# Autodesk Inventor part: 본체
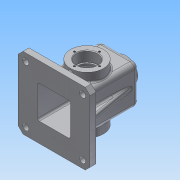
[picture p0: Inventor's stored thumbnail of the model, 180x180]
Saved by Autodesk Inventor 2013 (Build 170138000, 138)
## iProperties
Created: 2018-10
Part Number: 본체
Material: 알루미늄 6061
Document SubType Name: Modeling
Designer: Administrator
Density: 2.71 g/cm^3
Mass: 797.172 g
Surface Area: 899.5 cm^2
Volume: 294.16 cm^3
Author: Administrator
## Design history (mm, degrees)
sketch "스케치1"
  geometry: L1 (32.5, -32.5)-(-32.5, -32.5); L2 (-32.5, -32.5)-(-32.5, 32.5); L3 (-32.5, 32.5)-(32.5, 32.5); L4 (32.5, 32.5)-(32.5, -32.5); L5 (32.5, -32.5)-(-32.5, 32.5); L6 (-32.5, -32.5)-(32.5, 32.5); 1 further point
  constraints: 12 end point, 2 midpoint, 2 parallel, 1 horizontal, 1 perpendicular
  dimensions: "d0" = 65 distance of L2.end L3.end; "d1" = 65 distance of L1.end L2.end
extrude "돌출1" new body sketch "스케치1" stored distance "d2" = 110; taper "d3" = 0 deg
sketch "스케치2"
  geometry: L1 (-27.5, 27.5)-(27.5, 27.5); L2 (27.5, 27.5)-(27.5, -27.5); L3 (27.5, -27.5)-(-27.5, -27.5); L4 (-27.5, -27.5)-(-27.5, 27.5); L5 (-27.5, 27.5)-(27.5, -27.5); L6 (27.5, 27.5)-(-27.5, -27.5); 1 further point
  constraints: 12 end point, 2 midpoint, 2 parallel, 1 horizontal, 1 perpendicular
  dimensions: "d4" = 55 distance of L2.end L3.end; "d5" = 55 distance of L1.end L2.end
extrude "돌출2" cut sketch "스케치2" distance "d6" = 105; taper "d7" = 0 deg
fillet "모깎기1" dims "d8" = 8
sketch "스케치3"
  geometry: L1 (57, 0)-(49, 0) reference; C1 r 27.5 at (24.5, 55); 1 further point
  constraints: 1 centre point, 1 coincident
  dimensions: "d9" = 55 diameter of C1; "d10" = 55 distance from line of L1 C1.centre
extrude "돌출3" join sketch "스케치3" distance "d11" = 15; taper "d12" = 0 deg
sketch "스케치4"
  geometry: C1 r 27.5 at (0, 0) reference; 1 further point
  constraints: 1 coincident
hole "구멍1" sketch "스케치4" at (0, 0) diameter "d13" = 30; stored, may be unused: countersink angle "d17" = 90 deg, drill point angle "d19" = 0 deg; dims "d14" = 6, "d15" = 35, "d16" = 17, "d18" = 20
sketch "스케치5"
  geometry: C1 r 17.5 at (0, 0) reference; 1 further point
  constraints: 1 vertical alignment
  dimensions: "d20" = 21 distance of C1.centre point (0, 21)
hole "구멍2" sketch "스케치5" at (0, 21) diameter "d21" = 3.242; stored, may be unused: countersink angle "d25" = 90 deg, drill point angle "d27" = 118 deg; dims "d22" = 8, "d23" = 35, "d24" = 17, "d26" = 10
chamfer "모따기1" distance "d31" = 1; stored, may be unused: second distance "d32" = 2, angle "d33" = 45 deg
fillet "모깎기2" dims "d34" = 0.3
fillet "모깎기3" dims "d35" = 3
chamfer "모따기2" distance "d36" = 1; stored, may be unused: second distance "d37" = 2, angle "d38" = 45 deg
fillet "모깎기4" dims "d39" = 0.3
fillet "모깎기5" dims "d40" = 3
node "작업 평면1"
sketch "스케치6"
  geometry: C1 r 20 at (0, 0); 1 further point
  constraints: 1 centre point, 1 coincident
  dimensions: "d42" = 40 diameter of C1
extrude "돌출4" join sketch "스케치6" stored distance "d43" = 15; taper "d44" = 7 deg
sketch "스케치7"
  geometry: C1 r 20 at (0, 0) reference; 1 further point
  constraints: 1 coincident
hole "구멍3" sketch "스케치7" at (0, 0) diameter "d45" = 22.835; stored, may be unused: countersink angle "d49" = 90 deg, drill point angle "d51" = 118 deg; dims "d46" = 8, "d47" = 35, "d48" = 17, "d50" = 10
chamfer "모따기3" distance "d52" = 1; stored, may be unused: second distance "d53" = 2, angle "d54" = 45 deg
fillet "모깎기6" dims "d55" = 3
fillet "모깎기7" dims "d56" = 3
fillet "모깎기8" dims "d57" = 3
sketch "스케치8"
  geometry: L1 (-24.5, -32.5)-(24.5, -32.5) reference; L2 (32.5, -24.5)-(32.5, 24.5) reference; L3 (24.5, 32.5)-(-24.5, 32.5) reference; L4 (-32.5, 24.5)-(-32.5, -24.5) reference; L5 (60, 60)-(-60, 60); L6 (-60, 60)-(-60, -60); L7 (-60, -60)-(60, -60); L8 (60, -60)-(60, 60); L9 (60, 60)-(-60, -60); L10 (-60, 60)-(60, -60); A1 r 8 centre (24.5, -24.5) between (24.5, -32.5) and (32.5, -24.5) reference; A2 r 8 centre (24.5, 24.5) between (32.5, 24.5) and (24.5, 32.5) reference; A3 r 8 centre (-24.5, 24.5) between (-24.5, 32.5) and (-32.5, 24.5) reference; A4 r 8 centre (-24.5, -24.5) between (-32.5, -24.5) and (-24.5, -32.5) reference; 1 further point
  constraints: 12 end point, 2 midpoint, 2 parallel, 1 horizontal, 1 perpendicular
  dimensions: "d58" = 120 distance of L7.end L6.end; "d59" = 120 distance of L6.end L5.end
extrude "돌출5" join sketch "스케치8" distance "d60" = 10; taper "d61" = 0 deg
chamfer "모따기4" distance "d62" = 8; stored, may be unused: second distance "d63" = 2, angle "d64" = 45 deg
sketch "스케치9"
  geometry: L1 (-47.5, 47.5)-(47.5, 47.5); L2 (47.5, 47.5)-(47.5, -47.5); L3 (47.5, -47.5)-(-47.5, -47.5); L4 (-47.5, -47.5)-(-47.5, 47.5); L5 (-47.5, 47.5)-(47.5, -47.5); L6 (47.5, 47.5)-(-47.5, -47.5); 7 further points
  constraints: 12 end point, 5 coincident, 3 midpoint, 2 parallel, 1 horizontal, 1 perpendicular
  dimensions: "d65" = 95 distance of L2.end L3.end; "d66" = 95 distance of L1.end L2.end
hole "구멍4" sketch "스케치9" at (-47.5, 47.5), (47.5, 47.5), (-47.5, -47.5), (47.5, -47.5) diameter "d67" = 10; stored, may be unused: countersink angle "d71" = 90 deg, drill point angle "d73" = 118 deg; dims "d68" = 8, "d69" = 35, "d70" = 17, "d72" = 10
sketch "스케치10"
  geometry: L1 (-12.418, 65)-(-11.418, 64) reference; L2 (-11.418, 64)-(-11.418, 50) reference; L3 (-11.418, 50)-(-24.5, 50) reference; L4 (-27.5, 47)-(-27.5, -55) reference; L5 (-27.5, -55)-(-60, -55) reference; L6 (-60, -55)-(-60, -45) reference; L7 (-60, -45)-(-32.5, -45) reference; L8 (-32.5, -45)-(-32.5, 47) reference; L9 (-24.5, 55)-(-23.882, 55) reference; L10 (-20.904, 57.634)-(-20, 65) reference; L11 (-20, 65)-(-12.418, 65) reference; L12 (11.418, 64)-(12.418, 65) reference; L13 (12.418, 65)-(20, 65) reference; L14 (20, 65)-(20.904, 57.634) reference; L15 (23.882, 55)-(24.5, 55) reference; L16 (32.5, 47)-(32.5, -45) reference; L17 (32.5, -45)-(60, -45) reference; L18 (60, -45)-(60, -55) reference; L19 (60, -55)-(27.5, -55) reference; L20 (27.5, -55)-(27.5, 47) reference; L21 (24.5, 50)-(11.418, 50) reference; L22 (11.418, 50)-(11.418, 64) reference; L23 (-48, -45)-(-41.054, -5.608); L24 (-48, -45)-(-8, -45); A1 r 3 centre (-24.5, 47) between (-24.5, 50) and (-27.5, 47) reference; A2 r 8 centre (-24.5, 47) between (-24.5, 55) and (-32.5, 47) reference; A3 r 3 centre (-23.882, 58) between (-23.882, 55) and (-20.904, 57.634) reference; A4 r 3 centre (23.882, 58) between (20.904, 57.634) and (23.882, 55) reference; A5 r 8 centre (24.5, 47) between (32.5, 47) and (24.5, 55) reference; A6 r 3 centre (24.5, 47) between (27.5, 47) and (24.5, 50) reference; 1 further point
  constraints: 4 end point, 1 equal length, 1 horizontal, 1 point on line
  dimensions: "d74" = 40 distance of L23.start L23.end; "d75" = 80 deg angle of L24 L23; "d76" = 12 distance of L6.end L23.start
feature "리브1" sketch "스케치10" dims "d77" = 1, "d78" = 10, "d79" = 0, "d80" = 0, "d81" = 1, "d82" = 1
sketch "스케치11"
  geometry: L1 (-21, -36.526)-(-22.621, -37.5) reference; L2 (-22.621, -37.5)-(-22.621, -47.5) reference; L3 (-22.621, -47.5)-(-27.5, -47.5) reference; L4 (-27.5, -47.5)-(-27.5, -35.5) reference; L5 (-30.5, -32.5)-(-45, -32.5) reference; L6 (-45, -32.5)-(-45, -60) reference; L7 (-45, -60)-(-55, -60) reference; L8 (-55, -60)-(-55, -27.5) reference; L9 (-55, -27.5)-(-15, -27.5) reference; L10 (-15, -27.5)-(-15, -30.5) reference; L11 (-15, -30.5)-(-17.2, -30.5) reference; L12 (-17.5, -30.8)-(-17.5, -46.5) reference; L13 (-17.5, -46.5)-(-18.5, -47.5) reference; L14 (-18.5, -47.5)-(-19.379, -47.5) reference; L15 (-19.379, -47.5)-(-19.379, -37.5) reference; L16 (-19.379, -37.5)-(-21, -36.526) reference; L17 (22.621, -37.5)-(21, -36.526) reference; L18 (21, -36.526)-(19.379, -37.5) reference; L19 (19.379, -37.5)-(19.379, -47.5) reference; L20 (19.379, -47.5)-(18.5, -47.5) reference; L21 (18.5, -47.5)-(17.5, -46.5) reference; L22 (17.5, -46.5)-(17.5, -30.8) reference; L23 (17.2, -30.5)-(15, -30.5) reference; L24 (15, -30.5)-(15, -27.5) reference; L25 (15, -27.5)-(47, -27.5) reference; L26 (50, -24.5)-(50, -11.418) reference; L27 (50, -11.418)-(64, -11.418) reference; L28 (64, -11.418)-(65, -12.418) reference; L29 (65, -12.418)-(65, -20) reference; L30 (65, -20)-(57.634, -20.904) reference; L31 (55, -23.882)-(55, -24.5) reference; L32 (47, -32.5)-(30.5, -32.5) reference; L33 (27.5, -35.5)-(27.5, -47.5) reference; L34 (27.5, -47.5)-(22.621, -47.5) reference; L35 (22.621, -47.5)-(22.621, -37.5) reference; L36 (-22.621, 37.5)-(-21, 36.526) reference; L37 (-21, 36.526)-(-19.379, 37.5) reference; L38 (-19.379, 37.5)-(-19.379, 47.5) reference; L39 (-19.379, 47.5)-(-18.5, 47.5) reference; L40 (-18.5, 47.5)-(-17.5, 46.5) reference; L41 (-17.5, 46.5)-(-17.5, 30.8) reference; L42 (-17.2, 30.5)-(-15, 30.5) reference; L43 (-15, 30.5)-(-15, 27.5) reference; L44 (-15, 27.5)-(-55, 27.5) reference; L45 (-55, 27.5)-(-55, 60) reference; L46 (-55, 60)-(-45, 60) reference; L47 (-45, 60)-(-45, 32.5) reference; L48 (-45, 32.5)-(-30.5, 32.5) reference; L49 (-27.5, 35.5)-(-27.5, 47.5) reference; L50 (-27.5, 47.5)-(-22.621, 47.5) reference; L51 (-22.621, 47.5)-(-22.621, 37.5) reference; L52 (21, 36.526)-(22.621, 37.5) reference; L53 (22.621, 37.5)-(22.621, 47.5) reference; L54 (22.621, 47.5)-(27.5, 47.5) reference; L55 (27.5, 47.5)-(27.5, 35.5) reference; L56 (30.5, 32.5)-(47, 32.5) reference; L57 (55, 24.5)-(55, 23.882) reference; L58 (57.634, 20.904)-(65, 20) reference; L59 (65, 20)-(65, 12.418) reference; L60 (65, 12.418)-(64, 11.418) reference; L61 (64, 11.418)-(50, 11.418) reference; L62 (50, 11.418)-(50, 24.5) reference; L63 (47, 27.5)-(15, 27.5) reference; L64 (15, 27.5)-(15, 30.5) reference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; A1 r 3 centre (-30.5, -35.5) between (-27.5, -35.5) and (-30.5, -32.5) reference; A2 r 0.3 centre (-17.2, -30.8) between (-17.2, -30.5) and (-17.5, -30.8) reference; A3 r 0.3 centre (17.2, -30.8) between (17.5, -30.8) and (17.2, -30.5) reference; A4 r 3 centre (47, -24.5) between (47, -27.5) and (50, -24.5) reference; A5 r 3 centre (58, -23.882) between (57.634, -20.904) and (55, -23.882) reference; A6 r 8 centre (47, -24.5) between (47, -32.5) and (55, -24.5) reference; A7 r 3 centre (30.5, -35.5) between (30.5, -32.5) and (27.5, -35.5) reference; A8 r 0.3 centre (-17.2, 30.8) between (-17.5, 30.8) and (-17.2, 30.5) reference; A9 r 3 centre (-30.5, 35.5) between (-30.5, 32.5) and (-27.5, 35.5) reference; A10 r 3 centre (30.5, 35.5) between (27.5, 35.5) and (30.5, 32.5) reference; A11 r 8 centre (47, 24.5) between (55, 24.5) and (47, 32.5) reference; A12 r 3 centre (58, 23.882) between (55, 23.882) and (57.634, 20.904) reference; A13 r 3 centre (47, 24.5) between (50, 24.5) and (47, 27.5) reference; A14 r 0.3 centre (17.2, 30.8) between (17.2, 30.5) and (17.5, 30.8) reference; 1 further point
  constraints: 2 end point, 1 perpendicular, 1 point on line
  dimensions: "d83" = 15 distance from line of L72.start L44
feature "리브2" sketch "스케치11" dims "d84" = 1, "d85" = 6, "d86" = 0, "d87" = 0, "d88" = 1, "d89" = 1
fillet "모깎기9" dims "d90" = 3
fillet "모깎기10" dims "d91" = 3
fillet "모깎기11" dims "d92" = 1
sketch "스케치12"
  geometry: L1 (-8, 0)-(-8, -91) reference; L2 (4.5, 18)-(44.5, 18) reference; 1 further point
  constraints: 1 other
  dimensions: "d93" = 32.5 distance from line of L1 point (24.5, -8); "d94" = 26 distance from line of L2 point (24.5, -8)
feature "엠보싱1" sketch "스케치12" dims "d4" = 55, "d40" = 3, "d46" = 8, "d94" = 26, "d95" = 0.5, "d96" = 0
node "솔리드1"
pattern_circular "원형 패턴1" dims angle "d29" = 360 deg
mirror "대칭1"
mirror "대칭2"
mirror "대칭3"
node "절단 모서리 투영1"
node "절단 모서리 투영2"
